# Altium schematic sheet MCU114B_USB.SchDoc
size 431 x 279 mm; Date: Not shown in title block; ApprovedBy: Not shown in title block; CheckedBy: Not shown in title block; Author: Not shown in title block; CompanyName: Not shown in title block; Engineer: Not shown in title block; Organization: Not shown in title block; Address1: Not shown in title block; Address2: Not shown in title block; Address3: Not shown in title block; Address4: Not shown in title block; DocumentNumber: 7; Revision: Use project parameter SCH_Rev; SheetNumber: 7; SheetTotal: 11; PageSetup: Record=PageOptions¦CenterHorizontal=True¦CenterVertical=True¦PrintScale=1.00¦XCorrection=1.00¦YCorrection=1.00¦PrintKind=0¦BorderSize=5000000¦LeftOffset=0¦BottomOffset=0¦Orientation=2¦PaperLength=1000¦PaperWidth=1000¦Scale=100¦PaperSource=15¦PrintQuality=600¦MediaType=1¦DitherType=10¦PaperKind=Letter¦PrintScaleMode=1
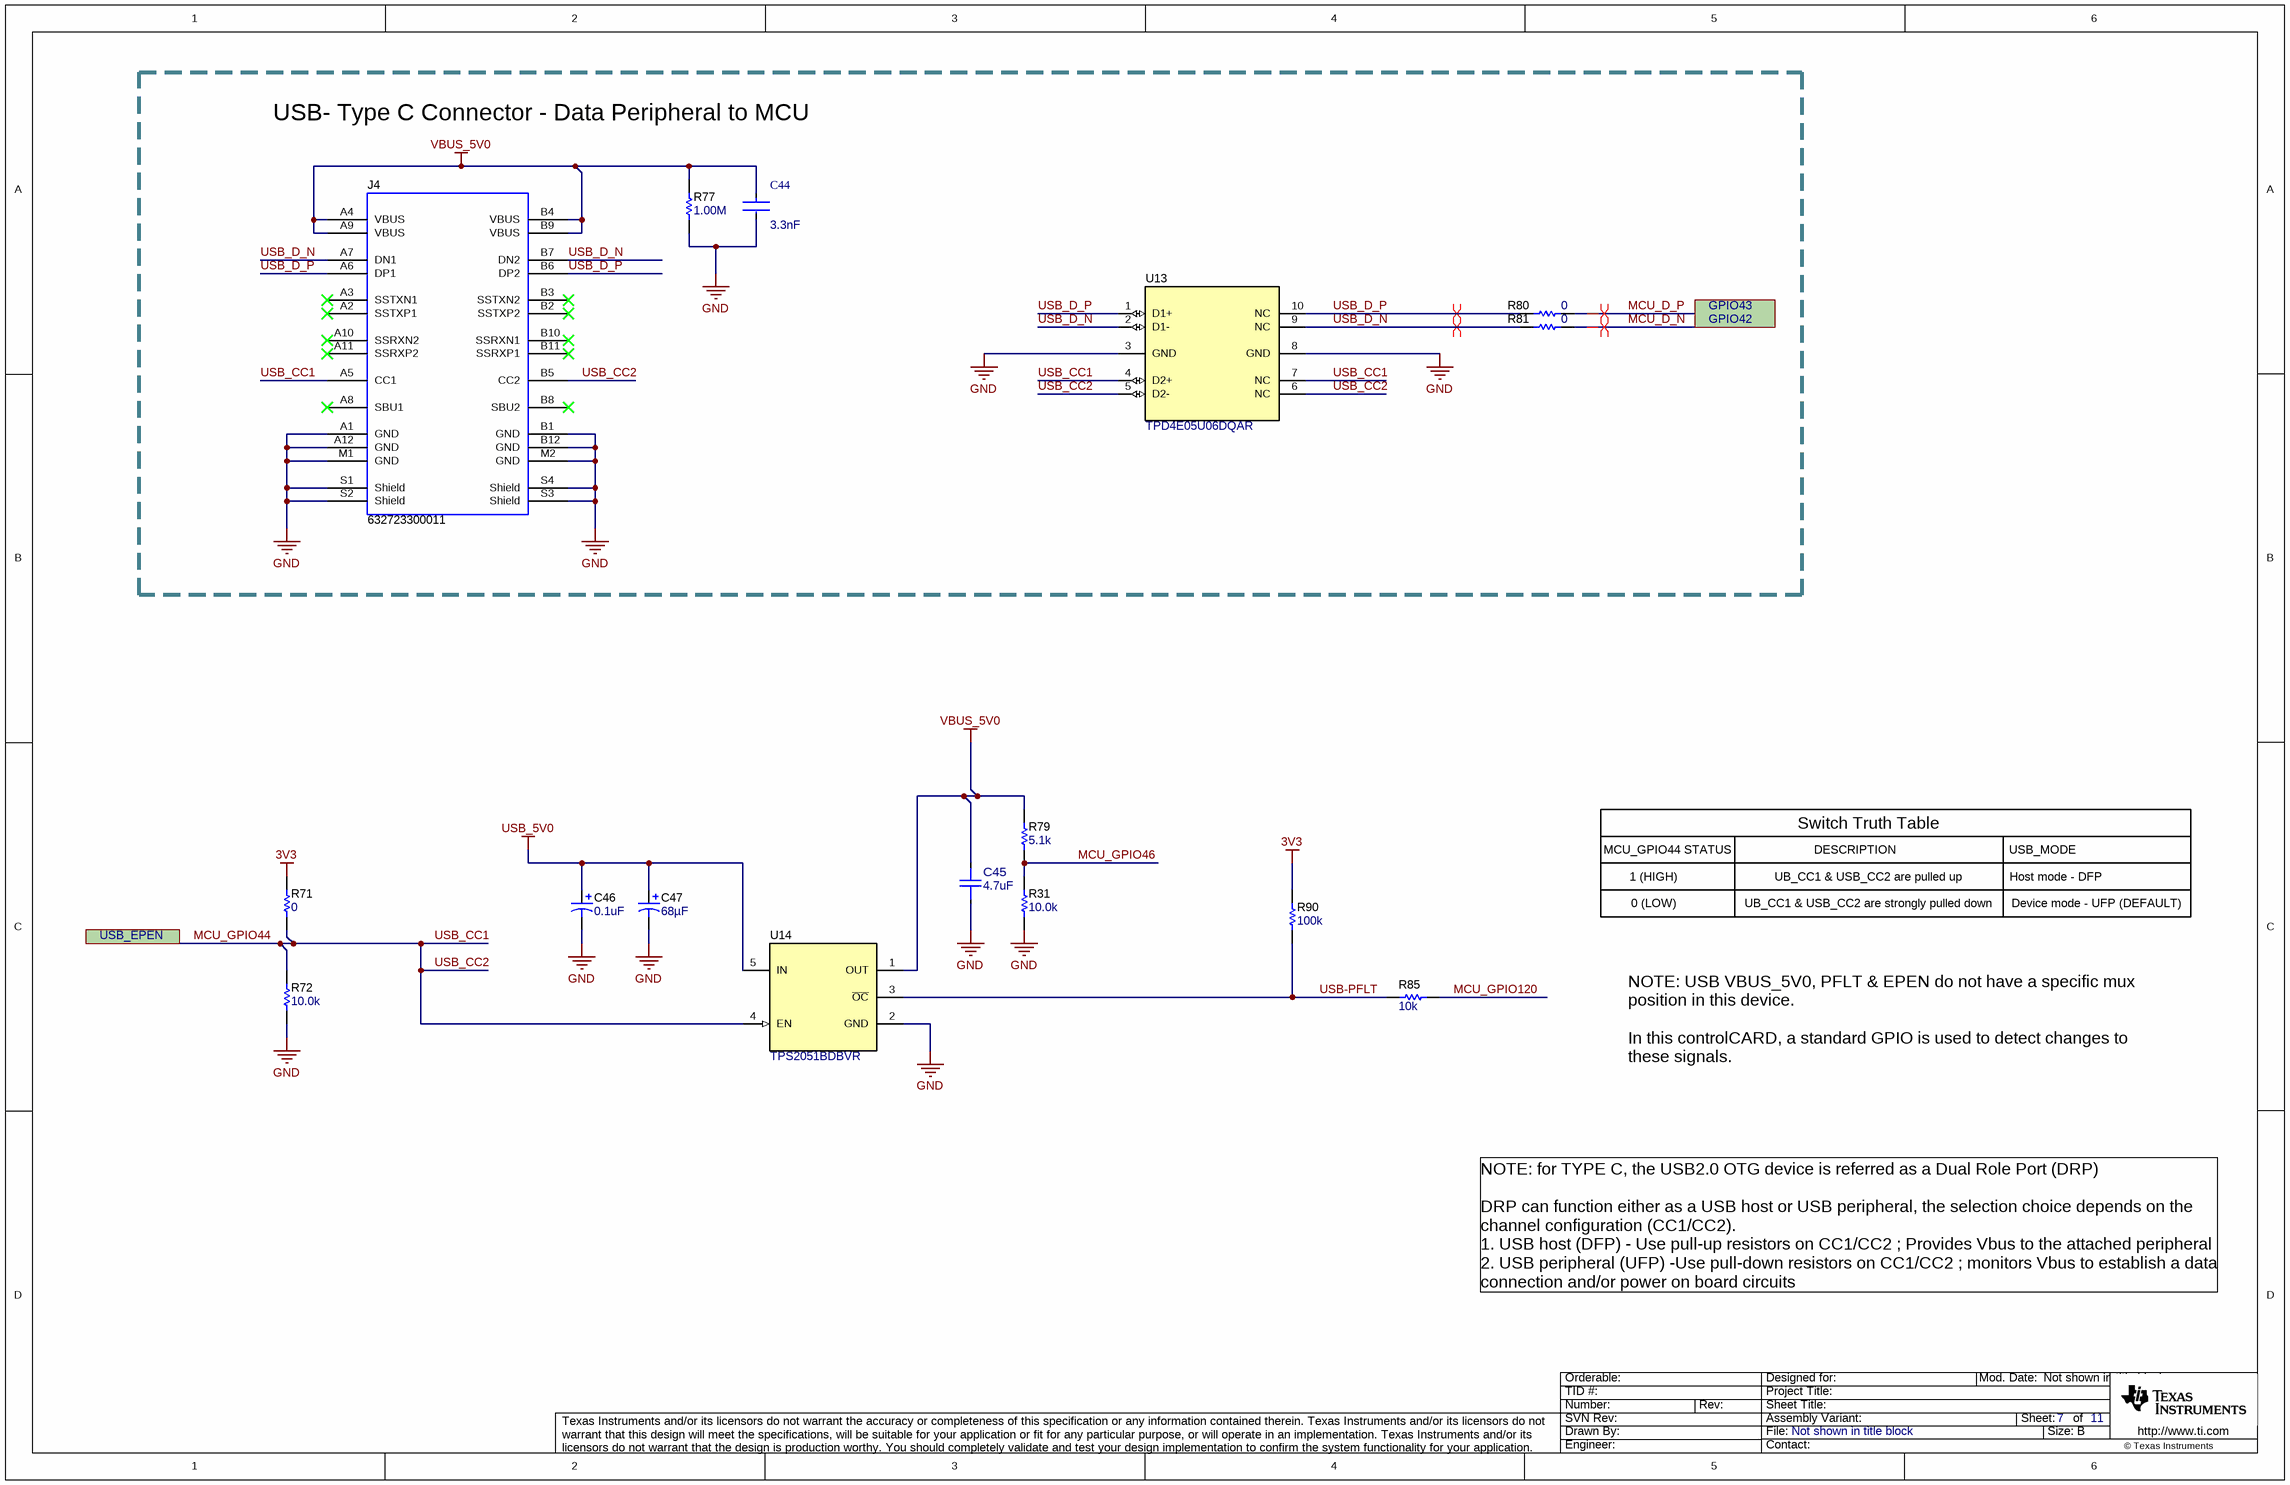
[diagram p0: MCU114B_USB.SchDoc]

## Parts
C44  Capacitance: 3.3nF  [FP-CL388-IPC_C]  (hidden comment: CL05B332KB5NNNC)
C45  ValueDisplayed: 4.7uF  [FP-885012106012_0603-MFG]  (hidden comment: 885012106012)
C46  ValueDisplayed: 0.1uF  [3216-18]  (hidden comment: 293D104X9035A2TE3)
C47  ValueDisplayed: 68µF  [3216-18]  (hidden comment: TLJA686M010R1500)
J4  632723300011  [Wurth_632_723_300_011]
R31  ValueDisplayed: 10.0k  [0402]  (hidden comment: AC0402FR-0710KL)
R71  ValueDisplayed: 0  [0402]  (hidden comment: CRCW04020000Z0EDHP)
R72  ValueDisplayed: 10.0k  [0402]  (hidden comment: AC0402FR-0710KL)
R77  ValueDisplayed: 1.00M  [0402]  (hidden comment: RMCF0402FT1M00)
R79  ValueDisplayed: 5.1k  [0603]  (hidden comment: RC0603JR-075K1L)
R80  ValueDisplayed: 0  [0402]  (hidden comment: ERJ-2GE0R00X)
R81  ValueDisplayed: 0  [0402]  (hidden comment: ERJ-2GE0R00X)
R85  ValueDisplayed: 10k  [0805_HV]  (hidden comment: ERJ-6GEYJ103V)
R90  ValueDisplayed: 100k  [0603]  (hidden comment: CRCW0603100KJNEA)
U13  TPD4E05U06DQAR  [DQA0010A]
U14  TPS2051BDBVR  [DBV0005A_N]

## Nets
3V3: R71.1 R90.2
GND: C44.2 C45.1 C46.2(-) C47.2(-) J4.A1(GND) J4.A12(GND) J4.B1(GND) J4.B12(GND) J4.M1(GND) J4.M2(GND) J4.S1(Shield) J4.S2(Shield) J4.S3(Shield) J4.S4(Shield) R31.1 R72.1 R77.1 U13.3(GND) U13.8(GND) U14.2(GND)
USB_5V0: C46.1(+) C47.1(+) U14.5(IN)
VBUS_5V0: C44.1 C45.2 J4.A4(VBUS) J4.A9(VBUS) J4.B4(VBUS) J4.B9(VBUS) R77.2 R79.2 U14.1(OUT)
MCU_D_N: R81.2
MCU_D_P: R80.2
MCU_GPIO44: J4.A5(CC1) J4.B5(CC2) R71.2 R72.2 U13.4(D2+) U13.5(D2-) U13.6(NC) U13.7(NC) U14.4(EN)  [also labelled USB_CC1, USB_CC2]
MCU_GPIO46: R31.2 R79.1
MCU_GPIO120: R85.2
USB-PFLT: R85.1 R90.1 U14.3(~{OC})
USB_D_N: J4.A7(DN1) J4.B7(DN2) R81.1 U13.2(D1-) U13.9(NC)
USB_D_P: J4.A6(DP1) J4.B6(DP2) R80.1 U13.1(D1+) U13.10(NC)

Not connected (* = marked no-connect by the designer): J4 A2(SSTXP1)* A3(SSTXN1)* A8(SBU1)* A10(SSRXN2)* A11(SSRXP2)* B2(SSTXP2)* B3(SSTXN2)* B8(SBU2)* B10(SSRXN1)* B11(SSRXP1)*

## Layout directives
differential pair: MCU_D_N, MCU_D_P, USB_D_N, USB_D_P

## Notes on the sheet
- USB- Type C Connector - Data Peripheral to MCU
- GPIO42
- GPIO43
- Switch Truth Table
- 0 (LOW)
- 1 (HIGH)
- MCU_GPIO44 STATUS
- DESCRIPTION
- UB_CC1 & USB_CC2 are pulled up
- UB_CC1 & USB_CC2 are strongly pulled down
- USB_MODE
- Host mode - DFP
- Device mode - UFP (DEFAULT)
- USB_EPEN
- NOTE: USB VBUS_5V0, PFLT & EPEN do not have a specific mux position in this device.
  In this controlCARD, a standard GPIO is used to detect changes to these signals.
- NOTE: for TYPE C, the USB2.0 OTG device is referred as a Dual Role Port (DRP)
  DRP can function either as a USB host or USB peripheral, the selection choice depends on the channel configuration (CC1/CC2).
  1. USB host (DFP) - Use pull-up resistors on CC1/CC2 ; Provides Vbus to the attached peripheral
  2. USB peripheral (UFP) -Use pull-down resistors on CC1/CC2 ; monitors Vbus to establish a data connection and/or power on board circuits

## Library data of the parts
C44 = CMP-13271-000627-1: Cap Ceramic 3.3nF 50V X7R ±10% SMD 0402 +125°C Paper T/R
C45 = CMP-0097305-1: 4.7 µF ±20% 10V Ceramic Capacitor X5R 0603 (1608 Metric); Manufacturer: Wurth Electronics; Cap_F: 4.7µF; Value: 4.7µF; AEC Qualified: No; SizeZ_mm: 0.87mm; TempCo: 15%
C46 = CMP-0011440-2: CAP, TA, 0.1 uF, 35 V, +/- 10%, 20 ohm, SMD; Manufacturer: Vishay-Sprague; TaMin_C: -55°C; ESR_ohm: 20; Polarized: Y; SizeAreaWB_mm2: 10.92; Value1: 20 ohm; U/M: EA; Value: 0.1uF; TaMax_C: 125°C; SizeZ_mm: 1.8; SizeX_mm: 3.2; SizeY_mm: 1.6; Cap_Case: A; Value2: 35V; SizeArea_mm2: 5.12; CompType: Capacitor; Cap_F: 100nF; IRMS_A: 60mA; AEC Category: Q200
C47 = CMP-0081926-1: CAP, TA, 68 µF, 10 V, +/- 20%, 1.5 ohm, SMD; Manufacturer: AVX; TaMin_C: -55°C; ESR_ohm: 1.5; Polarized: Y; SizeAreaWB_mm2: 10.92; Value1: 1.5 ohm; Value: 68uF; TaMax_C: 125°C; SizeZ_mm: 1.8; SizeX_mm: 3.2; SizeY_mm: 1.6; Value2: 10V; SizeArea_mm2: 5.12; CompType: Capacitor; AEC Qualified: N; IRMS_A: 224mA; AEC Category: Q200
J4 = CMP-0080891-1: Connector, Receptacle, USB Type C, R/A; Manufacturer: Wurth Elektronik; Current_A: 3A; Gender: Female; Voltage_V: 5V; ContactFinish: Gold; Cert_UL: Y
R31 R72 = CMP-0077731-1: RES, 10.0 k, 1%, 0.063 W, AEC-Q200 Grade 0, 0402; Manufacturer: Yageo America; Power_W: 63mW; TempCo: 100 ppm/C; Value_Code: 10k0; U/M: EA; Value: 10.0k; EIA_Code: E96; Res_ohm: 10k; SizeX_mm: 1.0; SizeY_mm: 0.5; SizeZ_mm: 0.6; Value2: 0.063W; AEC Qualified: Y; VDC_V: 50V; AEC Grade: 0; AEC Category: Q200
R71 = CMP-0081856-1: RES, 0, 0%, 0.2 W, AEC-Q200 Grade 0, 0402; Manufacturer: Vishay-Dale; SizeAreaWB_mm2: 3; SizeArea_mm2: 0.5; AEC Qualified: Y; AEC Category: Q200; Value: 0; SizeZ_mm: 0.6; Power_W: 200mW; VDC_V: 50V; Value2: 0.2W; SizeX_mm: 1
R77 = CMP-0026757-1: RES, 1.00 M, 1%, 0.063 W, AEC-Q200 Grade 0, 0402; Manufacturer: Stackpole Electronics Inc; Power_W: 63mW; TempCo: 100 ppm/C; Value_Code: 1M00; U/M: EA; Value: 1.00Meg; EIA_Code: E96; Res_ohm: 1M; SizeX_mm: 1; SizeY_mm: 0.5; SizeZ_mm: 0.6; Value2: 0.063W; AEC Qualified: Y; VDC_V: 50V; AEC Grade: 0; AEC Category: Q200
R79 = CMP-0025932-5: RES, 5.1 k, 5%, 0.1 W, 0603; Manufacturer: Yageo; Power_W: 100mW; TempCo: 100 ppm/C; Value_Code: 5k10; Value: 5.1k; EIA_Code: E24; SizeX_mm: 1.6; SizeY_mm: 0.8; SizeZ_mm: 1; Value2: 0.1W; SizeArea_mm2: 1.28; AEC Qualified: N; VDC_V: 75V; AEC Category: Q200; SizeAreaWB_mm2: 4.68
R80 R81 = CMP-0026992-3: RES, 0, 5%, 0.1 W, AEC-Q200 Grade 0, 0402; Manufacturer: Panasonic; Power_W: 100mW; TempCo: 600 ppm/C; Value_Code: 0000; Value: 0; EIA_Code: E24; SizeX_mm: 1; SizeY_mm: 0.5; SizeZ_mm: 0.6; Value2: 0.1W; AEC Qualified: Y; VDC_V: 50V; AEC Category: Q200; SizeAreaWB_mm2: 3
R85 = CMP-0020620-3: RES, 10 k, 5%, 0.125 W, AEC-Q200 Grade 0, 0805; Manufacturer: Panasonic; Power_W: 125mW; TempCo: 200 ppm/C; Value_Code: 10k0; Value: 10k; EIA_Code: E24; SizeX_mm: 2; SizeY_mm: 1.25; SizeZ_mm: 1.45; Value2: 0.125W; SizeArea_mm2: 2.5; AEC Qualified: Y; VDC_V: 150V; AEC Category: Q200; AEC Grade: 0; SizeAreaWB_mm2: 6.75
R90 = CMP-0025698-4: RES, 100 k, 5%, 0.1 W, AEC-Q200 Grade 0, 0603; Manufacturer: Vishay-Dale; Power_W: 100mW; TempCo: 200 ppm/C; Value: 100k; EIA_Code: E24; SizeX_mm: 1.6; SizeY_mm: 0.8; SizeZ_mm: 1; Value2: 0.1W; SizeArea_mm2: 1.28; AEC Qualified: Y; VDC_V: 75V; AEC Category: Q200; AEC Grade: 0
U13 = CMP-0073613-3: 4-Channel Ultra-Low-Capacitance IEC ESD Protection Diode, DQA0010A (USON-10); Alternate Manufacturer: Texas Instruments; Green_Lifecycle: Active; SizeAreaWB_mm2: 7.0; Green_REACh: Passed; SizeZ_mm: 0.55; SizeX_mm: 1.0; SizeY_mm: 2.5; CompType: IC; AEC Category: Q200; AEC Qualified: N
U14 = CMP-0074276-1: Single, Current-Limited, Power-Distribution Switch, DBV0005A (SOT-23-5); Alternate PartNumber: TPS2051BDBVT; Alternate Manufacturer: Texas Instruments; Green_Lifecycle: Active; SizeAreaWB_mm2: 14.82; Green_REACh: Passed; U/M: EA; SizeZ_mm: 1.45; SizeX_mm: 2.8; SizeY_mm: 2.9; SizeArea_mm2: 8.12; CompType: IC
